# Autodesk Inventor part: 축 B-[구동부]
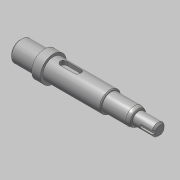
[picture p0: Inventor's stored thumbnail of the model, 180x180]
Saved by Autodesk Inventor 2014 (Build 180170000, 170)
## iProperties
Created: 2020-04
Part Number: 축 B-[구동부]
Material: 강철, 연강
Document SubType Name: Modeling
Designer: mduedu
Density: 7.86 g/cm^3
Appearance: 강철
Mass: 60.8598 g
Surface Area: 31.2859 cm^2
Volume: 7.74298 cm^3
Author: mduedu
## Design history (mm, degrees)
sketch "스케치1"
  geometry: L1 (0, 0)-(14, 0); L2 (14, 0)-(14, 6); L3 (14, 6)-(0, 6); L4 (0, 6)-(0, 0); L5 (14, 0)-(19, 0); L6 (19, 0)-(19, 7.5); L7 (19, 7.5)-(14, 7.5); L8 (14, 7.5)-(14, 0); L9 (19, 0)-(52, 0); L10 (52, 0)-(52, 6); L11 (52, 6)-(19, 6); L12 (19, 6)-(19, 0); L13 (52, 0)-(68, 0); L14 (68, 0)-(68, 5); L15 (68, 5)-(52, 5); L16 (52, 5)-(52, 0); L17 (68, 0)-(80, 0); L18 (80, 0)-(80, 3.5); L19 (80, 3.5)-(68, 3.5); L20 (68, 3.5)-(68, 0)
  constraints: 40 end point, 10 parallel, 5 horizontal, 5 perpendicular
  dimensions: "d0" = 80 distance between parallel lines of L18 L4; "d2" = 14 distance of L2.end L3.end; "d3" = 5 distance of L6.end L7.end; "d5" = 7 diameter of L19 L17; "d6" = 10 diameter of L15 L13; "d7" = 12 diameter of L11 L9; "d8" = 12 diameter of L3 L1; "d9" = 15 diameter of L7 L5; "d35" = 16 distance of L14.end L15.end; "d36" = 52 distance between parallel lines of L10 L4
revolve "회전1" sketch "스케치1" stored, may be unused: angle "d11" = 90 deg
sketch "스케치2"
  geometry: L1 (0, 6)-(0, -6) reference; L2 (0, -6)-(-14, -6) reference; L3 (-14, -6)-(-14, -7.5) reference; L4 (-14, -7.5)-(-19, -7.5) reference; L5 (-19, -7.5)-(-19, -6) reference; L6 (-19, -6)-(-52, -6) reference; L7 (-52, -6)-(-52, -5) reference; L8 (-52, -5)-(-68, -5) reference; L9 (-68, -5)-(-68, -3.5) reference; L10 (-68, -3.5)-(-80, -3.5) reference; L11 (-80, -3.5)-(-80, 3.5) reference; L12 (-80, 3.5)-(-68, 3.5) reference; L13 (-68, 3.5)-(-68, 5) reference; L14 (-68, 5)-(-52, 5) reference; L15 (-52, 5)-(-52, 6) reference; L16 (-52, 6)-(-19, 6) reference; L17 (-19, 6)-(-19, 7.5) reference; L18 (-19, 7.5)-(-14, 7.5) reference; L19 (-14, 7.5)-(-14, 6) reference; L20 (-14, 6)-(0, 6) reference; L21 (-80, 3.5)-(-72, 3.5); L22 (-72, 3.5)-(-72, 2.3); L23 (-72, 2.3)-(-80, 2.3); L24 (-80, 2.3)-(-80, 3.5); 1 further point
  constraints: 8 end point, 2 parallel, 1 horizontal, 1 perpendicular
  dimensions: "d37" = 8 distance of L22.end L23.end; "d38" = 1.2 distance of L21.end L22.end
extrude "돌출1" cut sketch "스케치2" stored distance "d14" = 2; taper "d15" = 0 deg
fillet "모깎기1" dims "d16" = 1
sketch "스케치3"
  geometry: L1 (0, -6)-(0, 6) reference; L2 (0, 6)-(14, 6) reference; L3 (14, 6)-(14, 7.5) reference; L4 (14, 7.5)-(19, 7.5) reference; L5 (19, 7.5)-(19, 6) reference; L6 (19, 6)-(52, 6) reference; L7 (52, 6)-(52, 5) reference; L8 (52, 5)-(68, 5) reference; L9 (68, 5)-(68, 3.5) reference; L10 (68, 3.5)-(80, 3.5) reference; L11 (80, 3.5)-(80, -3.5) reference; L12 (80, -3.5)-(68, -3.5) reference; L13 (68, -3.5)-(68, -5) reference; L14 (68, -5)-(52, -5) reference; L15 (52, -5)-(52, -6) reference; L16 (52, -6)-(19, -6) reference; L17 (19, -6)-(19, -7.5) reference; L18 (19, -7.5)-(14, -7.5) reference; L19 (14, -7.5)-(14, -6) reference; L20 (14, -6)-(0, -6) reference; L21 (23, 6)-(35, 6); L22 (35, 6)-(35, 3.5); L23 (35, 3.5)-(23, 3.5); L24 (23, 3.5)-(23, 6); 1 further point
  constraints: 8 end point, 2 parallel, 1 horizontal, 1 perpendicular, 1 point on line
  dimensions: "d17" = 12 distance of L22.end L23.end; "d18" = 2.5 distance of L21.end L22.end; "d19" = 4 distance from line of L24 L4.end
extrude "돌출2" cut sketch "스케치3" stored distance "d20" = 4; taper "d21" = 0 deg
fillet "모깎기2" dims "d22" = 2
chamfer "모따기1" distance "d23" = 1; stored, may be unused: second distance "d24" = 2, angle "d25" = 45 deg
chamfer "모따기2" distance "d26" = 0.5; stored, may be unused: second distance "d27" = 2, angle "d28" = 45 deg
fillet "모깎기3" dims "d29" = 0.3
chamfer "모따기3" distance "d30" = 1.39; stored, may be unused: second distance "d31" = 2, angle "d32" = 30 deg
fillet "모깎기4" dims "d33" = 4, "d34" = 0.5
node "솔리드1"
node "절단 모서리 투영2"
node "절단 모서리 투영3"
